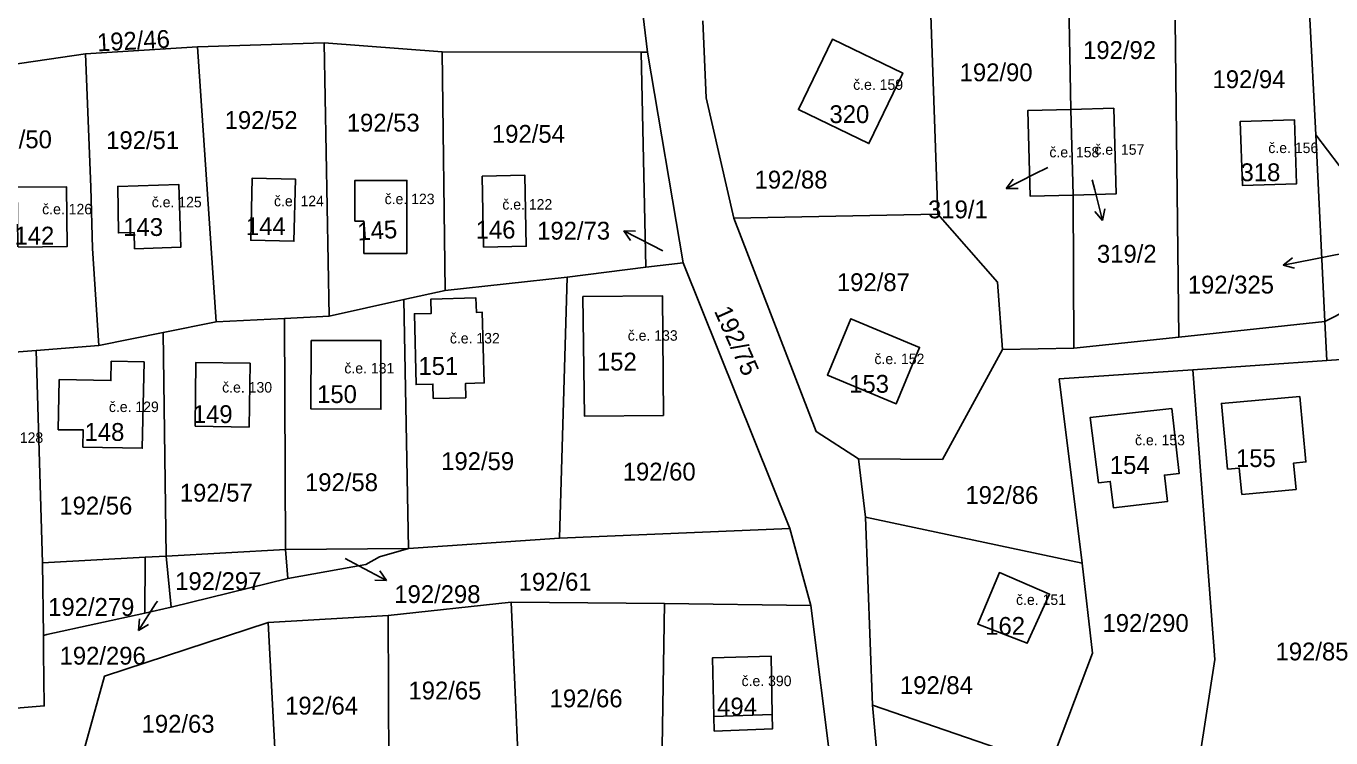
# Model space of a CAD drawing. Extents: x -887272 to -880188, y -1026687 to -1021896.
# Drawn here: x -882457.7 to -882333.3, y -1024238.2 to -1024170.3 of the extents above; entities that cross this region are included whole.
import ezdxf

# ---------------------------------------------------------------- set-up
doc = ezdxf.new("R2010")
doc.units = 0
for name, color, linetype in [('Definiční body', 7, 'Continuous'), ('Hranice parcel', 7, 'Continuous'), ('Parcelní čísla', 7, 'Continuous'), ('Polygon budovy', 7, 'Continuous'), ('Pop  PČ popisy', 7, 'Continuous'), ('Vnitřní kresba', 7, 'Continuous')]:
    doc.layers.add(name, color=color, linetype=linetype)

msp = doc.modelspace()

# ---------------------------------------------------------------- linework, layer by layer
at = {"layer": 'Hranice parcel'}
for p, q in [((-882398.41, -1024172.81), (-882399.41, -1024164.66)), ((-882358.04, -1024178.27), (-882358.24, -1024168.04)), ((-882370.74, -1024188.25), (-882371.41, -1024169.28)), ((-882347.76, -1024199.98), (-882348.11, -1024169.76)), ((-882335.28, -1024168.99), (-882334.7, -1024180.71)), ((-882452, -1024172.98), (-882441.31, -1024172.32)), ((-882441.31, -1024172.32), (-882429.24, -1024171.93)), ((-882439.54, -1024198.54), (-882441.31, -1024172.32)), ((-882429.24, -1024171.93), (-882417.98, -1024172.8)), ((-882428.76, -1024197.98), (-882429.24, -1024171.93)), ((-882464.49, -1024174.79), (-882452, -1024172.98)), ((-882417.98, -1024172.8), (-882399, -1024172.81)), ((-882417.69, -1024195.54), (-882417.98, -1024172.8)), ((-882399, -1024172.81), (-882398.41, -1024172.81)), ((-882398.58, -1024193.32), (-882399, -1024172.81)), ((-882395.01, -1024192.91), (-882398.41, -1024172.81)), ((-882357.82, -1024186.45), (-882358.04, -1024178.27)), ((-882333.83, -1024198.49), (-882334.7, -1024180.71)), ((-882357.75, -1024201.05), (-882357.82, -1024186.45)), ((-882370.74, -1024188.25), (-882390.17, -1024188.64)), ((-882406.07, -1024194.26), (-882398.58, -1024193.32)), ((-882395.01, -1024192.91), (-882398.58, -1024193.32)), ((-882384.85, -1024218.23), (-882395.01, -1024192.91)), ((-882417.69, -1024195.54), (-882406.07, -1024194.26)), ((-882406.81, -1024219.16), (-882406.07, -1024194.26)), ((-882421.63, -1024196.41), (-882417.69, -1024195.54)), ((-882428.76, -1024197.98), (-882421.63, -1024196.41)), ((-882421.19, -1024220.14), (-882421.63, -1024196.41)), ((-882439.54, -1024198.54), (-882433.01, -1024198.2)), ((-882433.01, -1024198.2), (-882428.76, -1024197.98)), ((-882432.93, -1024220.23), (-882433.01, -1024198.2)), ((-882333.83, -1024198.49), (-882347.76, -1024199.98)), ((-882333.83, -1024198.49), (-882333.65, -1024202.21)), ((-882450.72, -1024200.78), (-882444.57, -1024199.55)), ((-882444.57, -1024199.55), (-882439.54, -1024198.54)), ((-882444.31, -1024220.86), (-882444.57, -1024199.55)), ((-882456.7, -1024201.26), (-882450.72, -1024200.78)), ((-882347.76, -1024199.98), (-882357.75, -1024201.05)), ((-882464.21, -1024201.86), (-882456.7, -1024201.26)), ((-882456.08, -1024221.52), (-882456.7, -1024201.26)), ((-882357.75, -1024201.05), (-882364.57, -1024201.18)), ((-882333.65, -1024202.21), (-882346.41, -1024203.09)), ((-882333.65, -1024202.21), (-882321.52, -1024201.38)), ((-882359.15, -1024203.97), (-882346.41, -1024203.09)), ((-882356.96, -1024221.54), (-882359.15, -1024203.97)), ((-882441.55, -1024208.49), (-882436.39, -1024208.57)), ((-882378.28, -1024211.6), (-882377.61, -1024217.16)), ((-882356.96, -1024221.54), (-882377.61, -1024217.16)), ((-882377.61, -1024217.16), (-882376.96, -1024235.08)), ((-882406.81, -1024219.16), (-882384.85, -1024218.23)), ((-882382.84, -1024225.57), (-882384.85, -1024218.23)), ((-882421.19, -1024220.14), (-882406.81, -1024219.16)), ((-882446.3, -1024220.97), (-882444.31, -1024220.86)), ((-882444.31, -1024220.86), (-882432.93, -1024220.23)), ((-882443.83, -1024225.73), (-882444.31, -1024220.86)), ((-882432.93, -1024220.23), (-882421.19, -1024220.14)), ((-882432.7, -1024223), (-882432.93, -1024220.23)), ((-882456.08, -1024221.52), (-882446.3, -1024220.97)), ((-882456, -1024228.42), (-882456.08, -1024221.52)), ((-882443.83, -1024225.73), (-882432.7, -1024223)), ((-882446.34, -1024226.32), (-882443.83, -1024225.73)), ((-882411.4, -1024225.24), (-882423.15, -1024226.52)), ((-882410.38, -1024248.8), (-882411.4, -1024225.24)), ((-882396.78, -1024225.38), (-882411.4, -1024225.24)), ((-882397.17, -1024247.78), (-882396.78, -1024225.38)), ((-882396.78, -1024225.38), (-882382.84, -1024225.57)), ((-882382.84, -1024225.57), (-882380.49, -1024244.25)), ((-882423.15, -1024226.52), (-882434.56, -1024227.19)), ((-882423.04, -1024249.77), (-882423.15, -1024226.52)), ((-882433.35, -1024250.44), (-882434.56, -1024227.19)), ((-882455.98, -1024230.05), (-882456, -1024228.42)), ((-882360.05, -1024240.88), (-882376.96, -1024235.08)), ((-882376.96, -1024235.08), (-882374.46, -1024263.02))]:
    msp.add_line(p, q, dxfattribs=at)
for points in [[(-882393.14, -1024169.83), (-882392.82, -1024177.17), (-882390.17, -1024188.64)], [(-882384.02, -1024178.3), (-882377.3, -1024181.53), (-882374.07, -1024174.82), (-882380.78, -1024171.59), (-882384.02, -1024178.3)], [(-882450.72, -1024200.78), (-882451.31, -1024191.54), (-882451.49, -1024185.7), (-882452, -1024172.98)], [(-882358.04, -1024178.27), (-882362.14, -1024178.38), (-882361.92, -1024186.56), (-882357.82, -1024186.45)], [(-882357.82, -1024186.45), (-882353.73, -1024186.34), (-882353.95, -1024178.16), (-882358.04, -1024178.27)], [(-882341.69, -1024185.52), (-882336.54, -1024185.38), (-882336.72, -1024179.28), (-882341.9, -1024179.42), (-882341.69, -1024185.52)], [(-882334.7, -1024180.71), (-882324.68, -1024193.85), (-882333.83, -1024198.49)], [(-882410.1, -1024184.56), (-882414.17, -1024184.65), (-882414.04, -1024191.4), (-882409.97, -1024191.32), (-882410.1, -1024184.56)], [(-882458.45, -1024191.4), (-882453.75, -1024191.36), (-882453.8, -1024185.66), (-882458.5, -1024185.7), (-882458.45, -1024191.4)], [(-882443.09, -1024185.44), (-882448.92, -1024185.62), (-882448.86, -1024190.05), (-882447.36, -1024190.01), (-882447.31, -1024191.56), (-882442.91, -1024191.42), (-882443.09, -1024185.44)], [(-882432.12, -1024190.85), (-882431.98, -1024184.92), (-882436.1, -1024184.82), (-882436.24, -1024190.75), (-882432.12, -1024190.85)], [(-882426.3, -1024185.04), (-882426.31, -1024188.92), (-882425.46, -1024188.92), (-882425.45, -1024192), (-882421.34, -1024192), (-882421.34, -1024185.05), (-882426.3, -1024185.04)], [(-882364.57, -1024201.18), (-882365.05, -1024194.74), (-882370.74, -1024188.25)], [(-882390.17, -1024188.64), (-882382.32, -1024209), (-882378.28, -1024211.6)], [(-882413.98, -1024204.36), (-882414.17, -1024197.61), (-882414.72, -1024197.63), (-882414.77, -1024196.25), (-882419.06, -1024196.36), (-882419.03, -1024197.72), (-882420.63, -1024197.76), (-882420.48, -1024204.51), (-882418.87, -1024204.47), (-882418.84, -1024205.83), (-882415.73, -1024205.76), (-882415.76, -1024204.4), (-882413.98, -1024204.36)], [(-882396.87, -1024207.45), (-882396.99, -1024196.04), (-882404.57, -1024196.12), (-882404.42, -1024207.52), (-882396.87, -1024207.45)], [(-882372.47, -1024200.97), (-882379.02, -1024198.24), (-882381.26, -1024203.61), (-882374.7, -1024206.34), (-882372.47, -1024200.97)], [(-882430.47, -1024200.31), (-882430.5, -1024206.83), (-882423.82, -1024206.86), (-882423.82, -1024200.3), (-882430.47, -1024200.31)], [(-882364.57, -1024201.18), (-882370.29, -1024211.65), (-882378.28, -1024211.6)], [(-882454.59, -1024208.81), (-882452.2, -1024208.83), (-882452.23, -1024210.47), (-882446.58, -1024210.58), (-882446.41, -1024202.35), (-882449.54, -1024202.29), (-882449.57, -1024204.13), (-882454.5, -1024204.04), (-882454.59, -1024208.81)], [(-882436.39, -1024208.57), (-882436.3, -1024202.48), (-882441.46, -1024202.4), (-882441.55, -1024208.49)], [(-882346.41, -1024203.09), (-882344.31, -1024230.73), (-882346.59, -1024245.32)], [(-882341.76, -1024214.98), (-882336.58, -1024214.5), (-882336.82, -1024211.99), (-882335.64, -1024211.88), (-882336.22, -1024205.65), (-882343.69, -1024206.3), (-882343.11, -1024212.57), (-882341.99, -1024212.47), (-882341.76, -1024214.98)], [(-882349.12, -1024213.14), (-882347.72, -1024212.98), (-882348.42, -1024206.8), (-882356.2, -1024207.64), (-882355.4, -1024213.88), (-882354.29, -1024213.75), (-882353.99, -1024216.25), (-882348.83, -1024215.65), (-882349.12, -1024213.14)], [(-882432.7, -1024223), (-882425.25, -1024221.66), (-882423.95, -1024220.93), (-882421.19, -1024220.14)], [(-882446.34, -1024226.32), (-882446.3, -1024221.18), (-882446.3, -1024220.97)], [(-882360.05, -1024240.88), (-882355.97, -1024230.12), (-882356.96, -1024221.54)], [(-882360.08, -1024224.48), (-882364.86, -1024222.44), (-882366.92, -1024227.36), (-882362.2, -1024229.18), (-882360.08, -1024224.48)], [(-882456, -1024228.42), (-882455.67, -1024228.35), (-882446.34, -1024226.32)], [(-882434.56, -1024227.19), (-882450.17, -1024232.3), (-882452.28, -1024239.89)], [(-882466.28, -1024236), (-882455.92, -1024235.15), (-882455.98, -1024230.05)], [(-882392.06, -1024237.54), (-882386.5, -1024237.34), (-882386.53, -1024235.98), (-882386.63, -1024230.4), (-882392.22, -1024230.57), (-882392.09, -1024236.16), (-882392.06, -1024237.54)]]:
    msp.add_lwpolyline(points, dxfattribs=at)
at = {"layer": 'Polygon budovy'}
for points in [[(-882374.07, -1024174.82), (-882380.78, -1024171.59), (-882384.02, -1024178.3), (-882377.3, -1024181.53)], [(-882358.04, -1024178.27), (-882362.14, -1024178.38), (-882361.92, -1024186.56), (-882357.82, -1024186.45)], [(-882358.04, -1024178.27), (-882357.82, -1024186.45), (-882353.73, -1024186.34), (-882353.95, -1024178.16)], [(-882341.9, -1024179.42), (-882341.69, -1024185.52), (-882336.54, -1024185.38), (-882336.72, -1024179.28)], [(-882414.04, -1024191.4), (-882409.97, -1024191.32), (-882410.1, -1024184.56), (-882414.17, -1024184.65)], [(-882458.45, -1024191.4), (-882453.75, -1024191.36), (-882453.8, -1024185.66), (-882458.5, -1024185.7)], [(-882447.31, -1024191.56), (-882442.91, -1024191.42), (-882443.09, -1024185.44), (-882448.92, -1024185.62), (-882448.86, -1024190.05), (-882447.36, -1024190.01)], [(-882436.1, -1024184.82), (-882436.24, -1024190.75), (-882432.12, -1024190.85), (-882431.98, -1024184.92)], [(-882426.31, -1024188.92), (-882425.46, -1024188.92), (-882425.45, -1024192), (-882421.34, -1024192), (-882421.34, -1024185.05), (-882426.3, -1024185.04)], [(-882414.72, -1024197.63), (-882414.77, -1024196.25), (-882419.06, -1024196.36), (-882419.03, -1024197.72), (-882420.63, -1024197.76), (-882420.48, -1024204.51), (-882418.87, -1024204.47), (-882418.84, -1024205.83), (-882415.73, -1024205.76), (-882415.76, -1024204.4), (-882413.98, -1024204.36), (-882414.17, -1024197.61)], [(-882396.87, -1024207.45), (-882396.99, -1024196.04), (-882404.57, -1024196.12), (-882404.42, -1024207.52)], [(-882379.02, -1024198.24), (-882381.26, -1024203.61), (-882374.7, -1024206.34), (-882372.47, -1024200.97)], [(-882430.47, -1024200.31), (-882430.5, -1024206.83), (-882423.82, -1024206.86), (-882423.82, -1024200.3)], [(-882454.5, -1024204.04), (-882454.59, -1024208.81), (-882452.2, -1024208.83), (-882452.23, -1024210.47), (-882446.58, -1024210.58), (-882446.41, -1024202.35), (-882449.54, -1024202.29), (-882449.57, -1024204.13)], [(-882441.55, -1024208.49), (-882436.39, -1024208.57), (-882436.3, -1024202.48), (-882441.46, -1024202.4)], [(-882356.2, -1024207.64), (-882355.4, -1024213.88), (-882354.29, -1024213.75), (-882353.99, -1024216.25), (-882348.83, -1024215.65), (-882349.12, -1024213.14), (-882347.72, -1024212.98), (-882348.42, -1024206.8)], [(-882364.86, -1024222.44), (-882366.92, -1024227.36), (-882362.2, -1024229.18), (-882360.08, -1024224.48)], [(-882392.22, -1024230.57), (-882392.09, -1024236.16), (-882386.53, -1024235.98), (-882386.63, -1024230.4)]]:
    msp.add_lwpolyline(points, close=True, dxfattribs=at)
at = {"layer": 'Pop  PČ popisy'}
for p, q in [((-882361.53, -1024184.46), (-882364.2, -1024185.82)), ((-882360.23, -1024183.81), (-882361.53, -1024184.46)), ((-882364.2, -1024185.82), (-882363.54, -1024184.92)), ((-882364.2, -1024185.82), (-882363.08, -1024185.81)), ((-882356, -1024185), (-882355.77, -1024185.95)), ((-882355.77, -1024185.95), (-882355.04, -1024188.86)), ((-882355.04, -1024188.86), (-882355.77, -1024188.01)), ((-882355.04, -1024188.86), (-882354.8, -1024187.77)), ((-882398.01, -1024191.22), (-882400.68, -1024189.86)), ((-882400.68, -1024189.86), (-882399.56, -1024189.87)), ((-882400.68, -1024189.86), (-882400.02, -1024190.76)), ((-882396.94, -1024191.77), (-882398.01, -1024191.22)), ((-882330.55, -1024191.69), (-882334.87, -1024192.55)), ((-882337.82, -1024193.12), (-882336.93, -1024192.44)), ((-882334.87, -1024192.55), (-882337.82, -1024193.12)), ((-882337.82, -1024193.12), (-882336.74, -1024193.42)), ((-882427.22, -1024221.1), (-882425.94, -1024221.78)), ((-882425.94, -1024221.78), (-882423.29, -1024223.19)), ((-882423.29, -1024223.19), (-882424.41, -1024223.16)), ((-882423.29, -1024223.19), (-882423.94, -1024222.28)), ((-882445.32, -1024225.43), (-882446.95, -1024227.95)), ((-882445.14, -1024225.16), (-882445.32, -1024225.43)), ((-882446.95, -1024227.95), (-882446.83, -1024226.83)), ((-882446.95, -1024227.95), (-882445.99, -1024227.38))]:
    msp.add_line(p, q, dxfattribs=at)
at = {"layer": 'Vnitřní kresba'}
msp.add_line((-882392.09, -1024236.16), (-882386.53, -1024235.98), dxfattribs=at)

# ---------------------------------------------------------------- texts
at = {"layer": 'Definiční body'}
for s, p in [('č.e. 159', (-882378.8, -1024176.41)), ('č.e. 158', (-882360.09, -1024182.85)), ('č.e. 157', (-882355.8, -1024182.6)), ('č.e. 156', (-882339.22, -1024182.44)), ('č.e. 126', (-882456.12, -1024188.28)), ('č.e. 125', (-882445.67, -1024187.61)), ('č.e. 124', (-882434.02, -1024187.51)), ('č.e. 123', (-882423.47, -1024187.31)), ('č.e. 122', (-882412.25, -1024187.83)), ('č.e. 132', (-882417.25, -1024200.59)), ('č.e. 133', (-882400.29, -1024200.33)), ('č.e. 152', (-882376.77, -1024202.56)), ('č.e. 131', (-882427.31, -1024203.45)), ('č.e. 130', (-882438.96, -1024205.27)), ('č.e. 129', (-882449.76, -1024207.13)), ('č.e. 128', (-882460.78, -1024210.07)), ('č.e. 153', (-882351.93, -1024210.3)), ('č.e. 151', (-882363.27, -1024225.52)), ('č.e. 390', (-882389.44, -1024233.26))]:
    msp.add_text(s, height=1, dxfattribs=at).set_placement(p)
at = {"layer": 'Parcelní čísla'}
for s, rotation, p in [('192/46', 3, (-882450.85, -1024172.75)), ('145', 4, (-882426.01, -1024190.79)), ('192/75', 294, (-882392.09, -1024197.49))]:
    msp.add_text(s, height=1.7, rotation=rotation, dxfattribs=at).set_placement(p)
for s, p in [('192/92', (-882356.88, -1024173.47)), ('192/90', (-882368.65, -1024175.59)), ('192/94', (-882344.54, -1024176.25)), ('192/52', (-882438.72, -1024180.14)), ('320', (-882381.06, -1024179.58)), ('192/53', (-882427.08, -1024180.39)), ('192/54', (-882413.24, -1024181.46)), ('192/50', (-882462.15, -1024181.98)), ('192/51', (-882450.02, -1024182.06)), ('318', (-882341.87, -1024185.12)), ('192/88', (-882388.2, -1024185.82)), ('319/1', (-882371.66, -1024188.66)), ('142', (-882458.76, -1024191.16)), ('143', (-882448.39, -1024190.34)), ('144', (-882436.69, -1024190.26)), ('146', (-882414.79, -1024190.59)), ('192/73', (-882408.93, -1024190.69)), ('319/2', (-882355.56, -1024192.89)), ('192/87', (-882380.35, -1024195.6)), ('192/325', (-882346.9, -1024195.83)), ('151', (-882420.25, -1024203.59)), ('152', (-882403.23, -1024203.17)), ('150', (-882429.91, -1024206.27)), ('153', (-882379.18, -1024205.29)), ('149', (-882441.76, -1024208.18)), ('148', (-882452.08, -1024209.88)), ('192/59', (-882418.08, -1024212.66)), ('155', (-882342.3, -1024212.37)), ('192/60', (-882400.77, -1024213.66)), ('154', (-882354.33, -1024213.03)), ('192/58', (-882431.06, -1024214.67)), ('192/57', (-882443, -1024215.67)), ('192/86', (-882368.1, -1024215.89)), ('192/56', (-882454.48, -1024216.9)), ('192/297', (-882443.44, -1024224.1)), ('192/61', (-882410.69, -1024224.16)), ('192/298', (-882422.55, -1024225.34)), ('192/279', (-882455.55, -1024226.56)), ('162', (-882366.21, -1024228.37)), ('192/290', (-882355.03, -1024228.09)), ('192/296', (-882454.46, -1024231.21)), ('192/85', (-882338.53, -1024230.81)), ('192/65', (-882421.2, -1024234.53)), ('192/84', (-882374.34, -1024234.02)), ('192/64', (-882432.96, -1024235.97)), ('192/66', (-882407.74, -1024235.28)), ('494', (-882391.77, -1024236.06)), ('192/63', (-882446.64, -1024237.7))]:
    msp.add_text(s, height=1.7, dxfattribs=at).set_placement(p)

doc.saveas('drawing.dxf')
